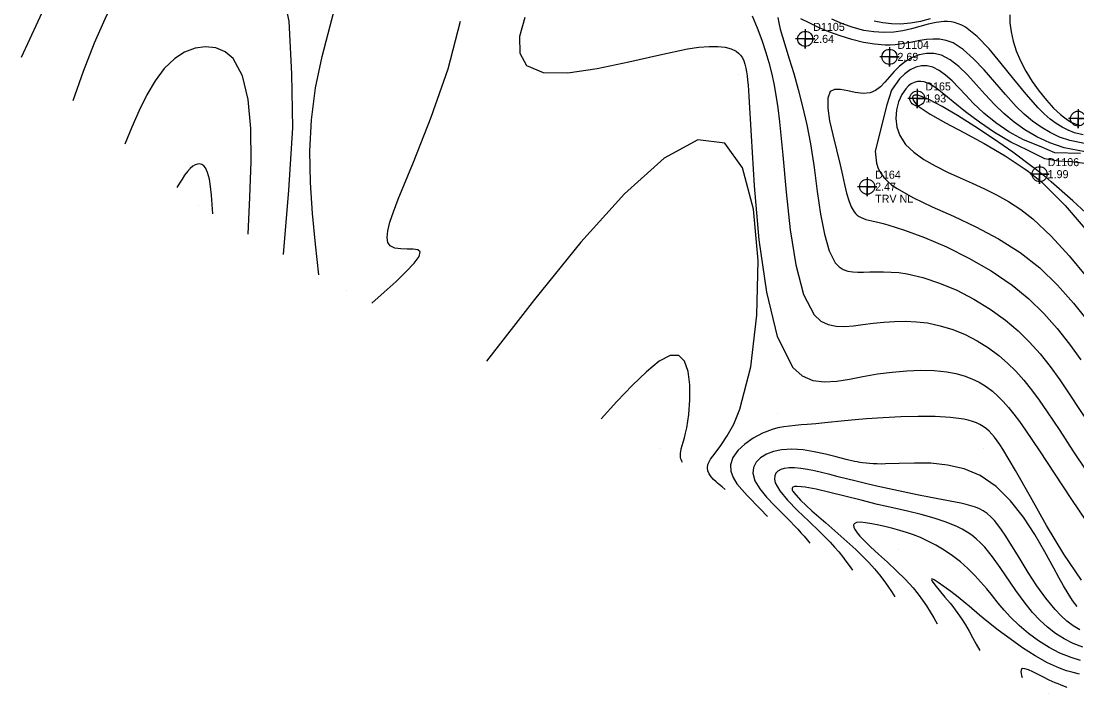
# Model space of a CAD drawing. Extents: x 2356077 to 2359823, y 225951 to 227822.
# Drawn here: x 2357126.3 to 2357456.1, y 226346.7 to 226556.7 of the extents above; entities that cross this region are included whole.
import ezdxf

# ---------------------------------------------------------------- set-up
doc = ezdxf.new("R2010")
doc.units = 0
for name, color, linetype in [('DTM Contours Major', 7, 'Continuous'), ('DTM Contours Minor', 7, 'Continuous'), ('Exist DTM Regular Point CELL', 7, 'Continuous'), ('Exist DTM Regular Point Cogo Comment', 7, 'Continuous'), ('Exist DTM Regular Point Cogo Elevation', 7, 'Continuous'), ('Exist DTM Regular Point Cogo Number', 7, 'Continuous'), ('PH Exist DTM Point', 7, 'Continuous')]:
    doc.layers.add(name, color=color, linetype=linetype)

msp = doc.modelspace()

# ---------------------------------------------------------------- linework, layer by layer
at = {"layer": 'DTM Contours Major'}
for points in [[(2357354.67, 226558.36), (2357356.27, 226554.68), (2357357.7, 226550.84), (2357358.97, 226546.94), (2357359.87, 226543.81), (2357360.69, 226540.6), (2357361.42, 226537.24), (2357362.08, 226533.63), (2357362.68, 226529.67), (2357363.22, 226525.28), (2357364.22, 226514.91), (2357365.25, 226503.36), (2357366.53, 226491.59), (2357368.28, 226480.62), (2357370.71, 226471.43), (2357374.06, 226465.01), (2357376.1, 226463.11), (2357378.39, 226461.98), (2357380.89, 226461.47), (2357383.56, 226461.4), (2357386.37, 226461.64), (2357389.29, 226462.01), (2357392.51, 226462.42), (2357395.81, 226462.76), (2357399.16, 226462.99), (2357402.55, 226463.05), (2357405.97, 226462.9), (2357409.41, 226462.5), (2357413.4, 226461.66), (2357417.34, 226460.44), (2357421.2, 226458.86), (2357424.92, 226456.97), (2357428.46, 226454.79), (2357431.77, 226452.35), (2357434.48, 226450), (2357437.04, 226447.44), (2357439.49, 226444.67), (2357441.9, 226441.65), (2357444.32, 226438.37), (2357446.8, 226434.8), (2357450.74, 226428.9), (2357454.88, 226422.62), (2357459.13, 226416.25)], [(2357458.09, 226521.22), (2357455.34, 226521.9), (2357453.4, 226522.65), (2357451.51, 226523.6), (2357449.65, 226524.78), (2357447.8, 226526.17), (2357445.94, 226527.8), (2357444.06, 226529.66), (2357440.28, 226533.9), (2357436.41, 226538.65), (2357432.51, 226543.51), (2357428.66, 226548.09), (2357424.91, 226551.99), (2357421.35, 226554.81), (2357420.19, 226555.45), (2357419.06, 226555.94), (2357417.93, 226556.28), (2357416.81, 226556.49), (2357415.67, 226556.59), (2357414.52, 226556.58), (2357412.15, 226556.29), (2357409.69, 226555.76), (2357404.46, 226554.37), (2357401.72, 226553.74), (2357398.89, 226553.31), (2357395.85, 226553.16), (2357392.72, 226553.35), (2357389.53, 226553.86), (2357386.26, 226554.7), (2357382.93, 226555.85), (2357379.54, 226557.3)], [(2357197.22, 226490.22), (2357197.8, 226501.77), (2357198.15, 226512.91), (2357198.03, 226523.21), (2357197.21, 226532.28), (2357195.46, 226539.69), (2357192.54, 226545.04), (2357190.04, 226547.18), (2357187.13, 226548.4), (2357183.95, 226548.74), (2357180.66, 226548.26), (2357177.39, 226547.02), (2357174.29, 226545.07), (2357171.04, 226541.98), (2357168.15, 226538.14), (2357165.54, 226533.71), (2357163.14, 226528.83), (2357160.9, 226523.65), (2357158.72, 226518.32)], [(2357461.63, 226494.34), (2357454.89, 226500.66), (2357448.12, 226506.56), (2357447.1, 226507.39), (2357446.09, 226508.21), (2357445.08, 226509.02), (2357444.07, 226509.82), (2357443.06, 226510.61), (2357442.03, 226511.39), (2357436.07, 226515.8), (2357430.04, 226520), (2357424.2, 226523.86), (2357418.77, 226527.26), (2357413.99, 226530.05), (2357410.1, 226532.12), (2357409.3, 226532.5), (2357408.57, 226532.83), (2357407.91, 226533.11), (2357407.31, 226533.33), (2357406.77, 226533.49), (2357406.3, 226533.59), (2357405.95, 226533.63), (2357405.65, 226533.62), (2357405.39, 226533.58), (2357405.18, 226533.5), (2357405.01, 226533.38), (2357404.89, 226533.22), (2357404.81, 226532.88), (2357404.87, 226532.45), (2357405.09, 226531.93), (2357405.48, 226531.35), (2357406.06, 226530.7), (2357406.83, 226530), (2357410.23, 226527.69), (2357415.03, 226525.01), (2357420.82, 226521.96), (2357427.18, 226518.53), (2357433.71, 226514.72), (2357440, 226510.51), (2357441.04, 226509.75), (2357442.05, 226508.97), (2357443.05, 226508.17), (2357444.04, 226507.36), (2357445.02, 226506.52), (2357445.99, 226505.66), (2357452.48, 226499.17), (2357458.72, 226491.9)], [(2357332.96, 226418.91), (2357332.72, 226419.35), (2357332.58, 226419.65), (2357332.51, 226419.81), (2357332.4, 226420.14), (2357332.31, 226420.5), (2357332.26, 226420.9), (2357332.24, 226421.34), (2357332.27, 226421.83), (2357332.35, 226422.38), (2357332.54, 226423.23), (2357332.81, 226424.21), (2357333.14, 226425.33), (2357333.5, 226426.62), (2357333.87, 226428.08), (2357334.23, 226429.72), (2357334.86, 226433.89), (2357335.21, 226438.54), (2357335.17, 226443.17), (2357334.66, 226447.34), (2357333.56, 226450.55), (2357331.79, 226452.35), (2357329.09, 226452.33), (2357325.66, 226450.53), (2357321.64, 226447.29), (2357317.19, 226442.98), (2357312.44, 226437.96), (2357307.54, 226432.58)], [(2357457.94, 226361.32), (2357454.96, 226362.48), (2357452.15, 226363.91), (2357449.48, 226365.59), (2357446.96, 226367.53), (2357444.57, 226369.72), (2357442.28, 226372.17), (2357439.6, 226375.49), (2357437.03, 226379.03), (2357432.13, 226386.2), (2357429.74, 226389.52), (2357427.33, 226392.47), (2357426.03, 226393.85), (2357424.69, 226395.1), (2357423.31, 226396.22), (2357421.85, 226397.24), (2357420.29, 226398.17), (2357418.62, 226399.01), (2357415.29, 226400.37), (2357411.57, 226401.57), (2357407.51, 226402.67), (2357403.16, 226403.72), (2357398.58, 226404.77), (2357393.8, 226405.88), (2357388.69, 226407.14), (2357383.65, 226408.41), (2357378.91, 226409.59), (2357374.69, 226410.57), (2357371.21, 226411.23), (2357368.69, 226411.48), (2357368.28, 226411.47), (2357367.93, 226411.42), (2357367.64, 226411.35), (2357367.42, 226411.25), (2357367.25, 226411.12), (2357367.16, 226410.95), (2357367.13, 226410.78), (2357367.14, 226410.59), (2357367.2, 226410.37), (2357367.3, 226410.13), (2357367.45, 226409.87), (2357367.64, 226409.57), (2357369.82, 226407.14), (2357373.31, 226403.9), (2357377.65, 226400.09), (2357382.37, 226395.95), (2357387.02, 226391.74), (2357391.13, 226387.68), (2357392.88, 226385.73), (2357394.42, 226383.88), (2357395.78, 226382.09), (2357397.01, 226380.36), (2357398.15, 226378.66), (2357399.25, 226376.99)]]:
    msp.add_lwpolyline(points, dxfattribs=at)
at = {"layer": 'DTM Contours Minor'}
for points in [[(2357208.27, 226483.89), (2357209.95, 226504), (2357211.15, 226523.39), (2357210.84, 226540.31), (2357210.09, 226556.68), (2357207.25, 226569.8), (2357201.88, 226578.92), (2357197.16, 226582.49), (2357191.64, 226584.42), (2357185.62, 226584.84), (2357179.42, 226583.85), (2357173.34, 226581.55), (2357167.7, 226578.05), (2357161.96, 226572.62), (2357157.06, 226565.95), (2357152.83, 226558.3), (2357149.11, 226549.9), (2357145.73, 226541.01), (2357142.51, 226531.87)], [(2357136.41, 226567.31), (2357131.5, 226556.65), (2357126.31, 226545.43)], [(2357219.33, 226477.55), (2357218.24, 226487.13), (2357217.32, 226496.73), (2357216.7, 226506.38), (2357216.55, 226516.11), (2357217.03, 226525.93), (2357218.29, 226535.87), (2357220.33, 226545.67), (2357222.8, 226555.3), (2357225.25, 226564.41)], [(2357235.84, 226468.64), (2357239.75, 226472.12), (2357243.43, 226475.47), (2357246.62, 226478.54), (2357249.1, 226481.19), (2357250.62, 226483.3), (2357250.95, 226484.71), (2357250.22, 226485.3), (2357248.79, 226485.52), (2357246.94, 226485.56), (2357244.94, 226485.62), (2357243.08, 226485.88), (2357241.63, 226486.54), (2357240.86, 226487.61), (2357240.61, 226489.19), (2357240.85, 226491.3), (2357241.54, 226493.97), (2357242.64, 226497.23), (2357244.12, 226501.11), (2357248.85, 226512.73), (2357254.42, 226526.74), (2357259.7, 226541.84), (2357263.59, 226556.75)], [(2357283.64, 226557.84), (2357282.03, 226551.92), (2357282.08, 226546.72), (2357284.18, 226542.88), (2357289.44, 226540.71), (2357297.1, 226540.59), (2357306.3, 226541.9), (2357316.17, 226544), (2357325.84, 226546.26), (2357334.44, 226548.04), (2357338.05, 226548.57), (2357341.21, 226548.83), (2357343.93, 226548.84), (2357346.23, 226548.59), (2357348.14, 226548.09), (2357349.66, 226547.35), (2357350.43, 226546.76), (2357351.07, 226546.08), (2357351.61, 226545.27), (2357352.05, 226544.34), (2357352.41, 226543.27), (2357352.71, 226542.04), (2357352.92, 226540.92), (2357353.1, 226539.68), (2357353.26, 226538.31), (2357353.4, 226536.79), (2357353.54, 226535.11), (2357353.66, 226533.25), (2357354.36, 226520.9), (2357355.31, 226505.35), (2357356.8, 226488.47), (2357359.11, 226472.14), (2357362.53, 226458.24), (2357367.33, 226448.63), (2357370.3, 226445.96), (2357373.61, 226444.54), (2357377.23, 226444.08), (2357381.09, 226444.32), (2357385.13, 226444.98), (2357389.29, 226445.8), (2357393.86, 226446.58), (2357398.44, 226447.19), (2357402.96, 226447.59), (2357407.36, 226447.75), (2357411.55, 226447.65), (2357415.48, 226447.25), (2357418.27, 226446.73), (2357420.87, 226446.01), (2357423.31, 226445.09), (2357425.59, 226443.99), (2357427.73, 226442.68), (2357429.75, 226441.19), (2357431.44, 226439.7), (2357433.09, 226438.03), (2357434.73, 226436.16), (2357436.41, 226434.07), (2357438.16, 226431.72), (2357440.03, 226429.09), (2357444.42, 226422.63), (2357449.24, 226415.33), (2357454.24, 226407.7), (2357459.17, 226400.27)], [(2357362.74, 226557.86), (2357362.97, 226556.23), (2357363.46, 226554.19), (2357364.16, 226551.8), (2357366.28, 226544.97), (2357367.66, 226540.39), (2357369.06, 226535.41), (2357370.43, 226530.07), (2357371.71, 226524.41), (2357372.86, 226518.44), (2357374.01, 226511.02), (2357375.02, 226503.59), (2357376.05, 226496.52), (2357377.23, 226490.2), (2357378.71, 226484.98), (2357380.65, 226481.24), (2357381.81, 226480.03), (2357383.11, 226479.21), (2357384.53, 226478.7), (2357386.07, 226478.43), (2357387.72, 226478.34), (2357389.46, 226478.36), (2357391.44, 226478.42), (2357393.53, 226478.47), (2357395.73, 226478.49), (2357398.06, 226478.41), (2357400.53, 226478.21), (2357403.14, 226477.83), (2357408.03, 226476.69), (2357413.22, 226474.96), (2357418.56, 226472.71), (2357423.89, 226469.98), (2357429.04, 226466.86), (2357433.86, 226463.39), (2357437.74, 226460.08), (2357441.31, 226456.55), (2357444.62, 226452.82), (2357447.75, 226448.88), (2357450.75, 226444.75), (2357453.7, 226440.43), (2357460.55, 226430.02)], [(2357458.48, 226518.49), (2357453.89, 226519.43), (2357450.7, 226520.54), (2357447.72, 226521.93), (2357444.92, 226523.59), (2357442.25, 226525.51), (2357439.68, 226527.68), (2357437.18, 226530.11), (2357433.78, 226533.8), (2357430.43, 226537.69), (2357427.12, 226541.51), (2357423.85, 226545), (2357420.62, 226547.89), (2357417.42, 226549.94), (2357415.32, 226550.73), (2357413.23, 226551.09), (2357411.16, 226551.15), (2357409.09, 226550.97), (2357407.02, 226550.64), (2357403.58, 226549.96), (2357402.19, 226549.71), (2357400.77, 226549.5), (2357399.31, 226549.34), (2357397.8, 226549.25), (2357396.22, 226549.24), (2357392.94, 226549.51), (2357389.46, 226550.1), (2357385.84, 226550.98), (2357382.19, 226552.1), (2357378.6, 226553.42), (2357375.15, 226554.89), (2357372.43, 226556.2), (2357369.93, 226557.46)], [(2357410.28, 226557.44), (2357407.3, 226556.59), (2357404.16, 226556.05), (2357400.98, 226555.83), (2357398.24, 226555.91), (2357395.52, 226556.22), (2357392.82, 226556.77)], [(2357435.15, 226558.72), (2357435.19, 226556.18), (2357435.55, 226553.41), (2357436.22, 226550.49), (2357437.19, 226547.46), (2357438.47, 226544.39), (2357440.18, 226541.07), (2357442.16, 226537.86), (2357444.32, 226534.82), (2357446.57, 226532.04), (2357448.84, 226529.59), (2357451.03, 226527.55), (2357451.89, 226526.85), (2357452.72, 226526.23), (2357453.53, 226525.69), (2357454.32, 226525.23), (2357455.09, 226524.86), (2357455.85, 226524.57), (2357456.86, 226524.31)], [(2357458.65, 226515.94), (2357452.1, 226517.22), (2357447.65, 226518.75), (2357443.59, 226520.61), (2357439.89, 226522.78), (2357436.48, 226525.22), (2357433.31, 226527.89), (2357430.34, 226530.76), (2357427.43, 226533.87), (2357424.63, 226536.98), (2357421.91, 226539.93), (2357419.21, 226542.54), (2357416.51, 226544.64), (2357413.77, 226546.07), (2357411.44, 226546.61), (2357409.11, 226546.65), (2357406.82, 226546.21), (2357404.61, 226545.37), (2357402.55, 226544.18), (2357400.66, 226542.7), (2357399.05, 226541.06), (2357397.57, 226539.35), (2357396.16, 226537.69), (2357394.73, 226536.21), (2357393.22, 226535.04), (2357391.54, 226534.33), (2357389.3, 226534.15), (2357386.9, 226534.48), (2357384.51, 226535), (2357382.29, 226535.42), (2357380.42, 226535.43), (2357379.08, 226534.74), (2357378.31, 226532.72), (2357378.31, 226529.6), (2357378.88, 226525.66), (2357379.84, 226521.2), (2357380.98, 226516.51), (2357382.12, 226511.89), (2357382.86, 226508.69), (2357383.53, 226505.73), (2357384.19, 226503.06), (2357384.87, 226500.72), (2357385.62, 226498.76), (2357386.49, 226497.23), (2357386.98, 226496.63), (2357387.51, 226496.14), (2357388.09, 226495.73), (2357388.73, 226495.39), (2357389.43, 226495.09), (2357390.19, 226494.84), (2357391.08, 226494.59), (2357392.07, 226494.35), (2357394.33, 226493.83), (2357395.63, 226493.52), (2357397.04, 226493.15), (2357402.31, 226491.52), (2357408.52, 226489.22), (2357415.33, 226486.28), (2357422.39, 226482.78), (2357429.36, 226478.77), (2357435.9, 226474.29), (2357441.1, 226470), (2357445.76, 226465.46), (2357449.97, 226460.73), (2357453.81, 226455.88), (2357457.34, 226450.97)], [(2357457.29, 226515.43), (2357449.24, 226515.58), (2357444.39, 226517.72), (2357439.4, 226519.71), (2357434.88, 226522.16), (2357430.78, 226524.97), (2357427.07, 226528.01), (2357423.73, 226531.17), (2357421.39, 226533.59), (2357419.2, 226535.91), (2357417.12, 226538.05), (2357415.1, 226539.89), (2357413.09, 226541.36), (2357411.06, 226542.34), (2357409.33, 226542.74), (2357407.58, 226542.73), (2357405.82, 226542.32), (2357404.07, 226541.52), (2357402.37, 226540.31), (2357400.73, 226538.7), (2357398.21, 226535.17), (2357396.78, 226530.57), (2357393.1, 226516.19), (2357393.49, 226512.38), (2357394.05, 226510.76), (2357394.82, 226509.3), (2357395.79, 226507.96), (2357396.97, 226506.73), (2357398.35, 226505.56), (2357399.94, 226504.45), (2357404.91, 226501.63), (2357410.89, 226498.79), (2357417.56, 226495.8), (2357424.59, 226492.52), (2357431.65, 226488.81), (2357438.39, 226484.54), (2357444.52, 226479.68), (2357450.07, 226474.33), (2357455.09, 226468.68), (2357459.62, 226462.93)], [(2357458.55, 226512.26), (2357454.4, 226512.77), (2357450.22, 226513.05), (2357446.07, 226513.73), (2357440.67, 226516.42), (2357435.45, 226518.99), (2357430.41, 226521.99), (2357425.65, 226525.22), (2357421.29, 226528.47), (2357417.44, 226531.56), (2357415.65, 226533.04), (2357414, 226534.39), (2357412.48, 226535.56), (2357411.06, 226536.54), (2357409.71, 226537.28), (2357408.4, 226537.74), (2357407.35, 226537.9), (2357406.32, 226537.86), (2357405.33, 226537.61), (2357404.38, 226537.15), (2357403.48, 226536.5), (2357402.63, 226535.64), (2357401.39, 226533.8), (2357400.42, 226531.54), (2357399.8, 226529.01), (2357399.6, 226526.31), (2357399.9, 226523.6), (2357400.79, 226521), (2357402.6, 226518.25), (2357405.15, 226515.79), (2357408.28, 226513.56), (2357411.84, 226511.52), (2357415.68, 226509.62), (2357419.64, 226507.82), (2357423.45, 226506.14), (2357427.24, 226504.4), (2357431.03, 226502.52), (2357434.8, 226500.38), (2357438.58, 226497.91), (2357442.37, 226494.98), (2357448.07, 226489.65), (2357453.71, 226483.47), (2357459.19, 226476.83)], [(2357346.21, 226410.53), (2357345.27, 226411.3), (2357344.34, 226412.08), (2357343.88, 226412.47), (2357343.43, 226412.87), (2357342.58, 226413.67), (2357341.82, 226414.5), (2357341.21, 226415.38), (2357340.81, 226416.3), (2357340.68, 226417.3), (2357340.87, 226418.37), (2357341.71, 226419.97), (2357343.09, 226421.89), (2357344.86, 226424.25), (2357346.85, 226427.22), (2357348.9, 226430.94), (2357350.85, 226435.55), (2357354.22, 226448.79), (2357356.16, 226464.95), (2357356.5, 226482.03), (2357355.05, 226498.01), (2357351.65, 226510.89), (2357346.1, 226518.66), (2357337.73, 226519.68), (2357327.16, 226513.95), (2357314.83, 226502.84), (2357301.19, 226487.68), (2357286.66, 226469.82), (2357271.69, 226450.61)], [(2357186.17, 226496.56), (2357185.99, 226499.53), (2357185.78, 226502.4), (2357185.49, 226505.08), (2357185.11, 226507.45), (2357184.58, 226509.43), (2357183.88, 226510.91), (2357183.34, 226511.55), (2357182.74, 226511.96), (2357182.07, 226512.14), (2357181.38, 226512.12), (2357180.65, 226511.89), (2357179.92, 226511.47), (2357179.08, 226510.74), (2357178.24, 226509.8), (2357177.4, 226508.69), (2357176.57, 226507.45), (2357175.75, 226506.13), (2357174.92, 226504.76)], [(2357457.52, 226382.26), (2357452.03, 226390.33), (2357446.66, 226399.25), (2357441.57, 226408.22), (2357436.95, 226416.45), (2357432.95, 226423.15), (2357432.05, 226424.52), (2357431.19, 226425.75), (2357430.35, 226426.85), (2357429.53, 226427.82), (2357428.7, 226428.68), (2357427.86, 226429.43), (2357426.87, 226430.17), (2357425.82, 226430.8), (2357424.71, 226431.33), (2357423.51, 226431.77), (2357422.2, 226432.14), (2357420.78, 226432.45), (2357416.62, 226433), (2357411.81, 226433.29), (2357406.57, 226433.34), (2357401.11, 226433.2), (2357395.64, 226432.93), (2357390.4, 226432.55), (2357386.87, 226432.24), (2357383.55, 226431.92), (2357377.42, 226431.3), (2357374.57, 226431.02), (2357371.84, 226430.79), (2357369.97, 226430.66), (2357368.14, 226430.51), (2357366.33, 226430.33), (2357364.53, 226430.08), (2357362.73, 226429.73), (2357360.91, 226429.24), (2357357.9, 226428.09), (2357354.99, 226426.56), (2357352.36, 226424.72), (2357350.19, 226422.67), (2357348.65, 226420.46), (2357347.92, 226418.18), (2357348.04, 226416.21), (2357348.76, 226414.25), (2357349.93, 226412.33), (2357351.42, 226410.47), (2357353.08, 226408.67), (2357357.19, 226404.49), (2357359.47, 226402.14)], [(2357456.2, 226374.03), (2357454.76, 226375.91), (2357453.35, 226378.04), (2357451.95, 226380.42), (2357450.49, 226383.04), (2357448.94, 226385.92), (2357446.15, 226391.03), (2357442.98, 226396.46), (2357439.4, 226401.89), (2357435.38, 226406.98), (2357430.89, 226411.42), (2357425.92, 226414.86), (2357420.94, 226416.95), (2357415.72, 226418.16), (2357410.46, 226418.69), (2357405.34, 226418.77), (2357400.58, 226418.63), (2357396.35, 226418.48), (2357395, 226418.46), (2357393.73, 226418.48), (2357392.52, 226418.52), (2357391.37, 226418.6), (2357390.24, 226418.71), (2357389.12, 226418.86), (2357388.31, 226418.99), (2357387.49, 226419.14), (2357386.65, 226419.31), (2357385.8, 226419.49), (2357384.92, 226419.7), (2357384.02, 226419.92), (2357380.93, 226420.71), (2357377.58, 226421.54), (2357374.09, 226422.3), (2357370.56, 226422.87), (2357367.1, 226423.13), (2357363.82, 226422.95), (2357361.34, 226422.42), (2357359.14, 226421.56), (2357357.31, 226420.41), (2357355.93, 226419.01), (2357355.09, 226417.4), (2357354.87, 226415.62), (2357355.53, 226413.24), (2357357.02, 226410.72), (2357359.13, 226408.13), (2357361.6, 226405.52), (2357366.67, 226400.52), (2357367.82, 226399.32), (2357368.9, 226398.17), (2357369.91, 226397.04), (2357370.88, 226395.93), (2357371.81, 226394.84), (2357372.73, 226393.76)], [(2357456.99, 226366.73), (2357454.93, 226368), (2357452.98, 226369.46), (2357451.11, 226371.14), (2357449.29, 226373.04), (2357446.42, 226376.55), (2357443.63, 226380.46), (2357440.93, 226384.59), (2357438.36, 226388.72), (2357435.95, 226392.66), (2357433.7, 226396.21), (2357432.57, 226397.91), (2357431.46, 226399.44), (2357430.36, 226400.8), (2357429.25, 226401.99), (2357428.1, 226403.01), (2357426.88, 226403.86), (2357425.68, 226404.5), (2357424.39, 226405.03), (2357423.01, 226405.47), (2357421.52, 226405.85), (2357419.91, 226406.2), (2357418.18, 226406.55), (2357410.52, 226408.03), (2357406.25, 226408.87), (2357401.85, 226409.76), (2357397.43, 226410.69), (2357393.12, 226411.66), (2357390.08, 226412.38), (2357387.15, 226413.1), (2357381.59, 226414.51), (2357378.94, 226415.18), (2357376.36, 226415.81), (2357374.1, 226416.33), (2357371.92, 226416.77), (2357369.85, 226417.11), (2357367.94, 226417.3), (2357366.2, 226417.32), (2357364.68, 226417.12), (2357363.61, 226416.77), (2357362.74, 226416.26), (2357362.1, 226415.59), (2357361.72, 226414.76), (2357361.64, 226413.78), (2357361.88, 226412.65), (2357363.31, 226410.1), (2357365.74, 226407.16), (2357368.86, 226403.95), (2357372.33, 226400.61), (2357375.82, 226397.27), (2357379.01, 226394.06), (2357380.43, 226392.51), (2357381.7, 226391.01), (2357382.87, 226389.56), (2357383.96, 226388.14), (2357384.99, 226386.75), (2357385.99, 226385.37)], [(2357457.29, 226357.1), (2357454.29, 226358.02), (2357450.82, 226359.44), (2357447.44, 226361.21), (2357444.17, 226363.28), (2357441.04, 226365.58), (2357438.11, 226368.08), (2357435.4, 226370.7), (2357433.41, 226372.88), (2357431.53, 226375.08), (2357429.72, 226377.29), (2357427.94, 226379.47), (2357426.13, 226381.61), (2357424.25, 226383.68), (2357422.05, 226385.86), (2357419.71, 226387.91), (2357417.25, 226389.81), (2357414.7, 226391.56), (2357412.07, 226393.14), (2357409.37, 226394.53), (2357407.23, 226395.49), (2357405.08, 226396.33), (2357402.92, 226397.08), (2357400.76, 226397.74), (2357398.62, 226398.34), (2357396.51, 226398.88), (2357394.21, 226399.41), (2357392.05, 226399.85), (2357390.11, 226400.15), (2357388.48, 226400.27), (2357387.25, 226400.18), (2357386.5, 226399.81), (2357386.31, 226399.34), (2357386.42, 226398.7), (2357386.82, 226397.92), (2357387.47, 226396.99), (2357388.36, 226395.95), (2357389.45, 226394.79), (2357391.65, 226392.66), (2357394.19, 226390.31), (2357396.94, 226387.8), (2357399.75, 226385.17), (2357402.47, 226382.48), (2357404.96, 226379.78), (2357406.51, 226377.89), (2357407.9, 226376.01), (2357409.16, 226374.15), (2357410.33, 226372.29), (2357411.43, 226370.44), (2357412.51, 226368.6)], [(2357456.94, 226352.88), (2357454.91, 226353.34), (2357452.83, 226353.95), (2357450.67, 226354.73), (2357446.92, 226356.45), (2357443.03, 226358.62), (2357439.1, 226361.13), (2357435.22, 226363.85), (2357431.5, 226366.65), (2357428.02, 226369.43), (2357426.86, 226370.39), (2357425.73, 226371.33), (2357422.49, 226374.07), (2357421.42, 226374.95), (2357419.01, 226376.91), (2357416.7, 226378.71), (2357414.59, 226380.28), (2357412.82, 226381.5), (2357411.51, 226382.3), (2357410.78, 226382.58), (2357410.67, 226382.39), (2357410.9, 226381.9), (2357411.43, 226381.15), (2357412.18, 226380.19), (2357413.1, 226379.07), (2357414.91, 226376.94), (2357415.7, 226376), (2357416.51, 226375.02), (2357417.32, 226374.01), (2357418.12, 226372.95), (2357418.92, 226371.85), (2357420.12, 226370.08), (2357421.29, 226368.22), (2357422.43, 226366.28), (2357423.55, 226364.29), (2357424.66, 226362.26), (2357425.76, 226360.22)], [(2357453.06, 226348.7), (2357451.22, 226349.44), (2357450.29, 226349.81), (2357449.37, 226350.2), (2357448.44, 226350.61), (2357447.5, 226351.03), (2357445.72, 226351.9), (2357443.99, 226352.77), (2357442.39, 226353.55), (2357440.99, 226354.18), (2357439.87, 226354.55), (2357439.1, 226354.59), (2357438.81, 226354.41), (2357438.67, 226354.07), (2357438.65, 226353.62), (2357438.72, 226353.07), (2357438.86, 226352.47), (2357439.02, 226351.83)]]:
    msp.add_lwpolyline(points, dxfattribs=at)
at = {"layer": 'Exist DTM Regular Point CELL'}
for points in [[(2357371.25, 226554.2), (2357371.25, 226548.2), (2357371.25, 226551.2), (2357374.25, 226551.2), (2357368.25, 226551.2)], [(2357397.57, 226548.58), (2357397.57, 226542.58), (2357397.57, 226545.58), (2357400.57, 226545.58), (2357394.57, 226545.58)], [(2357406.26, 226535.61), (2357406.26, 226529.61), (2357406.26, 226532.61), (2357409.26, 226532.61), (2357403.26, 226532.61)], [(2357456.46, 226529.29), (2357456.46, 226523.29), (2357456.46, 226526.29), (2357459.46, 226526.29), (2357453.46, 226526.29)], [(2357444.48, 226511.96), (2357444.48, 226505.96), (2357444.48, 226508.96), (2357447.48, 226508.96), (2357441.48, 226508.96)], [(2357390.6, 226508.05), (2357390.6, 226502.05), (2357390.6, 226505.05), (2357393.6, 226505.05), (2357387.6, 226505.05)]]:
    msp.add_lwpolyline(points, dxfattribs=at)
for centre in [(2357371.25, 226551.2), (2357397.57, 226545.58), (2357406.26, 226532.61), (2357456.46, 226526.29), (2357444.48, 226508.96), (2357390.6, 226505.05)]:
    msp.add_circle(centre, 2.34, dxfattribs=at)
at = {"layer": 'PH Exist DTM Point'}
for p, q in [((2357350.41, 226540.01), (2357350.41, 226540.01)), ((2357181.61, 226499.17), (2357181.61, 226499.17)), ((2357227.95, 226472.61), (2357227.95, 226472.61)), ((2357362.67, 226434.19), (2357362.67, 226434.19)), ((2357326.1, 226423.25), (2357326.1, 226423.25)), ((2357426.99, 226423.46), (2357426.99, 226423.46)), ((2357388.64, 226419.7), (2357388.64, 226419.7)), ((2357366.53, 226410.76), (2357366.53, 226410.76)), ((2357427.43, 226401.41), (2357427.43, 226401.41)), ((2357400.41, 226391.86), (2357400.41, 226391.86)), ((2357423.65, 226370.27), (2357423.65, 226370.27)), ((2357447.11, 226346.72), (2357447.11, 226346.72))]:
    msp.add_line(p, q, dxfattribs=at)

# ---------------------------------------------------------------- texts
at = {"layer": 'Exist DTM Regular Point Cogo Comment'}
msp.add_text('TRV NL', height=2.5, dxfattribs=at).set_placement((2357393.1, 226500.05))
at = {"layer": 'Exist DTM Regular Point Cogo Elevation'}
for s, p in [('2.64', (2357373.75, 226549.95)), ('2.69', (2357400.07, 226544.33)), ('1.93', (2357408.76, 226531.36)), ('1.99', (2357446.98, 226507.71)), ('2.47', (2357393.1, 226503.8))]:
    msp.add_text(s, height=2.5, dxfattribs=at).set_placement(p)
at = {"layer": 'Exist DTM Regular Point Cogo Number'}
for s, p in [('D1105', (2357373.75, 226553.7)), ('D1104', (2357400.07, 226548.08)), ('D165', (2357408.76, 226535.11)), ('D1106', (2357446.98, 226511.46)), ('D164', (2357393.1, 226507.55))]:
    msp.add_text(s, height=2.5, dxfattribs=at).set_placement(p)

doc.saveas('drawing.dxf')
